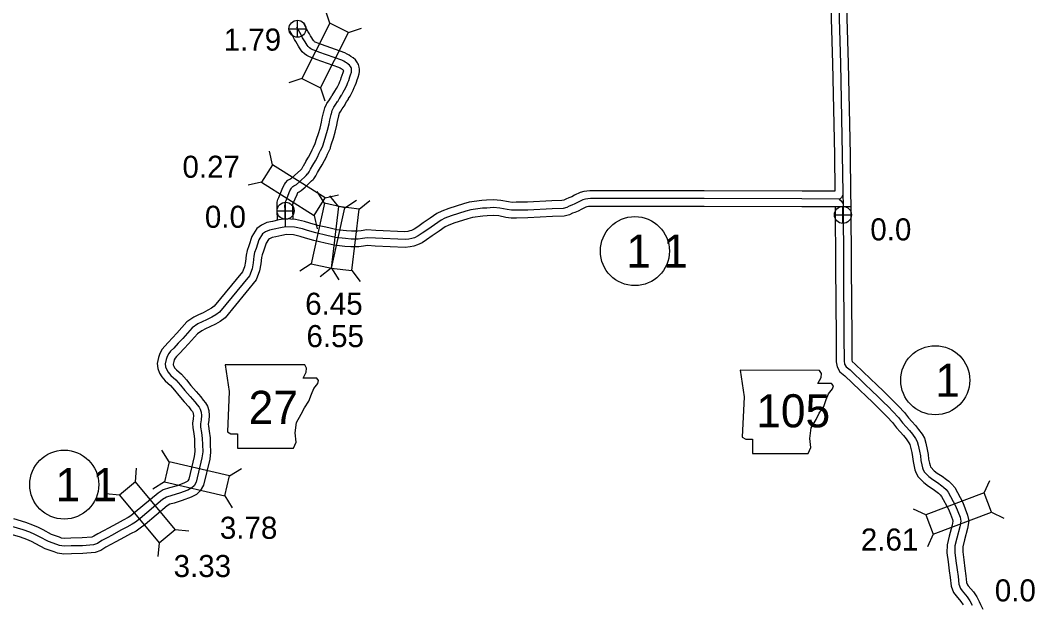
# Model space of a CAD drawing. Extents: x -83719 to 153526, y -11835 to 11446.
# Drawn here: x -1718 to -1071, y 1987 to 2360 of the extents above; entities that cross this region are included whole.
import ezdxf

# ---------------------------------------------------------------- set-up
doc = ezdxf.new("R2010")
doc.units = 0
for name, color, linetype in [('Level 10', 7, 'Continuous'), ('Level 20', 7, 'Continuous'), ('Level 21', 7, 'Continuous'), ('Level 25', 7, 'Continuous'), ('Level 26', 7, 'Continuous'), ('Level 27', 7, 'Continuous'), ('Level 58', 7, 'Continuous'), ('Level 59', 7, 'Continuous')]:
    doc.layers.add(name, color=color, linetype=linetype)

msp = doc.modelspace()

# ---------------------------------------------------------------- linework, layer by layer
at = {"layer": 'Level 10'}
for points in [[(-1193.62, 2424.2), (-1194.65, 2422.94), (-1195.29, 2421.32), (-1196.58, 2417.04), (-1198.52, 2408.98), (-1199.96, 2405.55), (-1201, 2401.06), (-1201.54, 2397.75), (-1201.69, 2394.1), (-1200.9, 2375.22), (-1199.7, 2332.04), (-1198.5, 2273.9), (-1198.17, 2250.64)], [(-1185.85, 2417.91), (-1185.89, 2417.86), (-1186.92, 2414.43), (-1188.99, 2405.85), (-1190.4, 2402.47), (-1191.18, 2399.11), (-1191.58, 2396.73), (-1191.68, 2394.1), (-1190.91, 2375.57), (-1189.7, 2332.28), (-1188.5, 2274.07), (-1188.15, 2249.59), (-1188.16, 2248.15)], [(-1543.62, 2232.75), (-1543.72, 2238.89), (-1543.79, 2241.37), (-1543.74, 2241.98), (-1543.73, 2242.22), (-1543.72, 2242.27), (-1543.47, 2242.95), (-1541.12, 2248.63), (-1540.52, 2249.71), (-1539.66, 2250.18), (-1538.37, 2251.09), (-1536.02, 2253.24), (-1531.81, 2257.15), (-1530.77, 2258.2), (-1530.42, 2258.56), (-1529.12, 2260.39), (-1527.97, 2262.56), (-1527.97, 2262.58), (-1526.78, 2264.62), (-1526.77, 2264.64), (-1524.99, 2267.54), (-1523.67, 2270.14), (-1522.42, 2272.66), (-1521.59, 2274.34), (-1519.67, 2278.15), (-1519.67, 2278.8), (-1519.09, 2280.85), (-1517.88, 2284.4), (-1516.77, 2288.27), (-1515.72, 2292.69), (-1515.3, 2295.04), (-1514.38, 2298.75), (-1514.36, 2298.85), (-1514.02, 2300.32), (-1513.26, 2301.8), (-1512.25, 2303.28), (-1510.5, 2305.83), (-1510.44, 2306.09), (-1509.55, 2307.59), (-1508.36, 2309.4), (-1508.22, 2309.69), (-1507.27, 2311.32), (-1506.33, 2313.07), (-1505.27, 2315.16), (-1504.6, 2316.72), (-1503.99, 2318.13), (-1503.45, 2319.61), (-1503.01, 2320.9), (-1502.98, 2320.96), (-1502.19, 2323.34), (-1501.55, 2325.5), (-1501.35, 2326.97), (-1501.31, 2328.41), (-1501.49, 2329.81), (-1501.92, 2331.41), (-1502.36, 2332.19), (-1502.51, 2332.63), (-1503.93, 2334.4), (-1505.3, 2335.68), (-1506.71, 2336.67), (-1507.8, 2337.34), (-1509.05, 2338.06), (-1510.67, 2338.81), (-1525.5, 2344.15), (-1527.92, 2345.02), (-1528.97, 2345.43), (-1529.61, 2345.76), (-1529.92, 2345.99), (-1530.25, 2346.31), (-1530.59, 2346.75), (-1531.11, 2347.52), (-1531.68, 2348.46), (-1532.49, 2349.78), (-1533.22, 2351.04), (-1533.95, 2352.35), (-1535.03, 2354.3), (-1535.94, 2356.02), (-1536.66, 2357.47)], [(-1553.61, 2232.06), (-1553.72, 2238.66), (-1553.8, 2241.66), (-1553.73, 2242.51), (-1553.71, 2243.58), (-1553.27, 2245.27), (-1552.78, 2246.6), (-1550.13, 2252.98), (-1549.08, 2254.89), (-1548.54, 2255.96), (-1546.94, 2257.58), (-1545.6, 2258.32), (-1544.98, 2258.67), (-1544.64, 2258.91), (-1542.8, 2260.59), (-1538.76, 2264.34), (-1538.12, 2264.98), (-1537.65, 2265.65), (-1537.12, 2266.65), (-1537.04, 2266.86), (-1535.33, 2269.81), (-1535.26, 2269.93), (-1533.72, 2272.42), (-1532.61, 2274.61), (-1531.39, 2277.1), (-1530.54, 2278.81), (-1529.45, 2280.96), (-1528.63, 2283.84), (-1527.42, 2287.39), (-1526.45, 2290.8), (-1525.51, 2294.72), (-1525.09, 2297.13), (-1524.22, 2300.59), (-1524.19, 2300.89), (-1524.07, 2301.27), (-1523.49, 2303.78), (-1522.28, 2306.13), (-1522.16, 2306.5), (-1520.49, 2308.95), (-1519.75, 2310.02), (-1518.85, 2311.53), (-1518.8, 2311.72), (-1517.07, 2314.36), (-1517.04, 2314.42), (-1515.99, 2316.2), (-1515.2, 2317.69), (-1514.34, 2319.39), (-1513.79, 2320.68), (-1513.28, 2321.85), (-1512.88, 2322.93), (-1512.27, 2324.73), (-1512.26, 2324.76), (-1511.73, 2326.34), (-1511.36, 2327.6), (-1511.35, 2327.65), (-1511.63, 2327.9), (-1512.22, 2328.32), (-1512.91, 2328.75), (-1513.65, 2329.17), (-1514.49, 2329.56), (-1528.88, 2334.74), (-1531.42, 2335.65), (-1533.12, 2336.31), (-1534.95, 2337.27), (-1536.4, 2338.35), (-1537.75, 2339.65), (-1538.68, 2340.88), (-1539.52, 2342.1), (-1540.22, 2343.26), (-1541.09, 2344.67), (-1541.92, 2346.12), (-1542.68, 2347.49), (-1543.81, 2349.53), (-1544.83, 2351.44), (-1545.61, 2353)], [(-1318.99, 2250.97), (-1354.38, 2250.97), (-1356.42, 2250.72), (-1358.22, 2250.5), (-1360.62, 2249.86), (-1364.18, 2248.06), (-1366, 2247.05), (-1367.75, 2246.42), (-1369.75, 2245.58), (-1370.96, 2244.94), (-1372.23, 2244.63), (-1378.67, 2244.42), (-1394.22, 2243.62), (-1401.46, 2243.53), (-1403.97, 2243.45), (-1406.26, 2243.81), (-1411.13, 2244.73), (-1415.91, 2245.16), (-1420.27, 2244.84), (-1423.32, 2244.78), (-1431.29, 2243.69), (-1435.03, 2242.61), (-1444.38, 2239.63), (-1448.82, 2237.95), (-1451.89, 2236.38), (-1456.26, 2233.33), (-1460.62, 2230.35), (-1464.2, 2227.95), (-1466.43, 2226.42), (-1468.08, 2225.61), (-1469.2, 2225.25), (-1470.55, 2224.95), (-1472.34, 2224.79), (-1490.82, 2225.55), (-1496.55, 2225.94), (-1500.14, 2225.37), (-1502.4, 2225.09), (-1506.44, 2225.06), (-1509.62, 2225.34), (-1515.8, 2226.08), (-1520.93, 2227.2), (-1527.92, 2228.85), (-1532.89, 2230.25), (-1536.39, 2231.39), (-1542.07, 2232.66), (-1548.45, 2233)], [(-1198.17, 2250.64), (-1219.16, 2250.67), (-1281.52, 2250.89), (-1318.97, 2250.97)], [(-1188.16, 2248.27), (-1188.03, 2242.66), (-1187.76, 2202.47), (-1187.49, 2157.59), (-1187.39, 2142.79), (-1187.25, 2142.06), (-1187.18, 2141.93), (-1185.24, 2140.32), (-1175.44, 2130.96), (-1171.37, 2127.04), (-1167.12, 2123.06), (-1163.94, 2119.88), (-1160.53, 2116.52), (-1157.55, 2113.53), (-1153.87, 2109.51), (-1151.24, 2106.02), (-1149.07, 2103.69), (-1146.85, 2101.11), (-1144.81, 2098.63), (-1142.65, 2095.58), (-1141.17, 2093.02), (-1140.22, 2089.81), (-1139.35, 2085.79), (-1138.77, 2082.55), (-1138.44, 2079.6), (-1137.98, 2077.15), (-1137.56, 2075.66), (-1137.31, 2074.86), (-1137.09, 2074.5), (-1134.92, 2072.27), (-1132.9, 2070.7), (-1129.9, 2068.83), (-1127.11, 2066.68), (-1125.65, 2065.62), (-1123.66, 2063.72), (-1121.83, 2061.52), (-1116.69, 2052.08), (-1115.12, 2048.05), (-1113.59, 2043.97), (-1112.82, 2040.22), (-1113.75, 2035.34), (-1115.62, 2028.12), (-1116.67, 2023.66), (-1116.73, 2020.46), (-1116.05, 2015.37), (-1115.33, 2009.79), (-1114.72, 2005.3), (-1114.27, 2000.97), (-1113.72, 1999.52), (-1113.16, 1998.76), (-1109.83, 1994.92), (-1107.78, 1991.72), (-1106.28, 1988.81), (-1105.29, 1986.89), (-1103.92, 1983.89)], [(-1318.99, 2240.97), (-1353.77, 2240.97), (-1355.19, 2240.79), (-1356.32, 2240.65), (-1357.04, 2240.46), (-1359.51, 2239.21), (-1361.87, 2237.91), (-1364.1, 2237.11), (-1365.48, 2236.52), (-1367.39, 2235.53), (-1370.84, 2234.67), (-1378.25, 2234.43), (-1393.9, 2233.63), (-1401.24, 2233.53), (-1404.59, 2233.43), (-1407.97, 2233.95), (-1412.51, 2234.82), (-1415.99, 2235.13), (-1419.81, 2234.84), (-1422.55, 2234.79), (-1429.21, 2233.88), (-1432.12, 2233.04), (-1441.09, 2230.19), (-1444.76, 2228.8), (-1446.72, 2227.79), (-1450.57, 2225.1), (-1455.01, 2222.07), (-1458.59, 2219.67), (-1461.38, 2217.76), (-1464.32, 2216.32), (-1466.58, 2215.59), (-1469.02, 2215.05), (-1472.09, 2214.77), (-1491.37, 2215.56), (-1496.1, 2215.88), (-1498.75, 2215.47), (-1501.75, 2215.1), (-1506.83, 2215.06), (-1510.65, 2215.39), (-1517.47, 2216.2), (-1523.14, 2217.45), (-1530.42, 2219.16), (-1535.8, 2220.68), (-1539.04, 2221.74), (-1543.43, 2222.72), (-1547.84, 2222.96)], [(-1188.02, 2240.63), (-1219.18, 2240.67), (-1281.54, 2240.89), (-1319, 2240.97)], [(-1198.02, 2240.56), (-1197.76, 2202.41), (-1197.49, 2157.52), (-1197.38, 2141.82), (-1196.76, 2138.56), (-1194.97, 2135.4), (-1191.89, 2132.85), (-1182.36, 2123.75), (-1178.26, 2119.79), (-1174.08, 2115.87), (-1170.99, 2112.79), (-1167.59, 2109.43), (-1164.78, 2106.61), (-1161.57, 2103.11), (-1158.91, 2099.58), (-1156.51, 2097.01), (-1154.5, 2094.67), (-1152.77, 2092.57), (-1151.08, 2090.17), (-1150.42, 2089.04), (-1149.92, 2087.34), (-1149.16, 2083.85), (-1148.67, 2081.11), (-1148.34, 2078.13), (-1147.73, 2074.87), (-1147.14, 2072.78), (-1146.47, 2070.66), (-1145.03, 2068.32), (-1141.6, 2064.8), (-1138.62, 2062.48), (-1135.61, 2060.61), (-1133.1, 2058.67), (-1132.07, 2057.92), (-1130.99, 2056.89), (-1130.15, 2055.88), (-1125.78, 2047.85), (-1124.46, 2044.47), (-1123.23, 2041.2), (-1123.02, 2040.16), (-1123.52, 2037.53), (-1125.33, 2030.52), (-1126.65, 2024.91), (-1126.74, 2019.9), (-1125.97, 2014.07), (-1125.24, 2008.48), (-1124.65, 2004.11), (-1124.09, 1998.65), (-1122.58, 1994.68), (-1120.95, 1992.48), (-1117.86, 1988.92), (-1116.46, 1986.73)], [(-1548.45, 2233), (-1552.66, 2232.26), (-1556.81, 2231.37), (-1560.26, 2230.62), (-1563.81, 2228.97), (-1566.78, 2226.83), (-1570, 2221.64), (-1571.9, 2215.7), (-1572.99, 2212.87), (-1573.55, 2209.89), (-1574.05, 2205.76), (-1574.64, 2202.41), (-1575.85, 2199.26), (-1593.9, 2177.23), (-1595.67, 2175.98), (-1597.89, 2174.65), (-1601.03, 2173.09), (-1603.84, 2171.76), (-1606.83, 2170.22), (-1611.27, 2167.21), (-1617.71, 2160.04), (-1620.47, 2156.99), (-1623.28, 2154), (-1625.4, 2151.83), (-1627.06, 2149.83), (-1628.56, 2147.1), (-1629.41, 2144.52), (-1630.22, 2140.67), (-1629.79, 2137.4), (-1628.7, 2134.48), (-1627.35, 2132.29), (-1625.21, 2129.58), (-1621.81, 2126.7), (-1619.14, 2123.72), (-1616.46, 2120.36), (-1613.03, 2116.34), (-1610.14, 2113), (-1608.72, 2111.19), (-1607.75, 2109.97), (-1607.55, 2109.6), (-1607.25, 2108.64), (-1607.11, 2107.42), (-1607.27, 2105.38), (-1607.68, 2102.62), (-1607.61, 2099.64), (-1606.98, 2096.02), (-1606.53, 2092.43), (-1606.44, 2088.91), (-1606.28, 2084.49), (-1606.67, 2081.37), (-1610.07, 2066.8), (-1610.65, 2065.8), (-1611.1, 2065.4), (-1612.78, 2064.5), (-1617.54, 2062.72), (-1622.35, 2061.26), (-1626.4, 2060.07), (-1629.75, 2057.93), (-1644.33, 2045.77), (-1647.11, 2043.57), (-1648.85, 2042.35), (-1651.86, 2040.77), (-1655.8, 2038.68), (-1661.37, 2035.63), (-1664.59, 2033.93), (-1668.01, 2032.05), (-1670.56, 2030.45), (-1671.9, 2029.98), (-1678.12, 2029.42), (-1685.3, 2029.3), (-1689.46, 2029.11), (-1691.28, 2029.35), (-1692.52, 2029.82), (-1697.56, 2031.63), (-1703.02, 2034.5), (-1706.04, 2036.07), (-1709.65, 2037.61), (-1714.05, 2039.35), (-1721.72, 2041.64)], [(-1547.84, 2222.96), (-1550.74, 2222.44), (-1554.71, 2221.59), (-1557.04, 2221.09), (-1558.73, 2220.3), (-1559.33, 2219.87), (-1560.85, 2217.42), (-1562.46, 2212.38), (-1563.33, 2210.12), (-1563.66, 2208.36), (-1564.16, 2204.28), (-1564.96, 2199.73), (-1567.09, 2194.18), (-1587.02, 2169.85), (-1590.21, 2167.59), (-1593.1, 2165.87), (-1596.66, 2164.1), (-1599.41, 2162.79), (-1601.73, 2161.61), (-1604.64, 2159.62), (-1610.28, 2153.34), (-1613.12, 2150.21), (-1616.06, 2147.08), (-1617.97, 2145.14), (-1618.75, 2144.19), (-1619.35, 2143.09), (-1619.74, 2141.92), (-1620.08, 2140.29), (-1620.02, 2139.83), (-1619.67, 2138.89), (-1619.14, 2138.03), (-1617.98, 2136.57), (-1614.82, 2133.89), (-1611.5, 2130.18), (-1608.74, 2126.72), (-1605.45, 2122.86), (-1602.42, 2119.37), (-1600.88, 2117.4), (-1599.37, 2115.5), (-1598.28, 2113.49), (-1597.42, 2110.72), (-1597.06, 2107.61), (-1597.33, 2104.24), (-1597.67, 2101.98), (-1597.63, 2100.63), (-1597.09, 2097.52), (-1596.54, 2093.18), (-1596.44, 2089.22), (-1596.26, 2084.04), (-1596.81, 2079.61), (-1600.68, 2063.03), (-1602.79, 2059.46), (-1605.25, 2057.17), (-1608.67, 2055.36), (-1614.34, 2053.24), (-1619.49, 2051.68), (-1622.21, 2050.88), (-1623.83, 2049.85), (-1638.03, 2038.01), (-1641.13, 2035.55), (-1643.63, 2033.8), (-1647.19, 2031.92), (-1651.06, 2029.87), (-1656.64, 2026.82), (-1659.84, 2025.13), (-1662.93, 2023.43), (-1666.21, 2021.37), (-1669.78, 2020.13), (-1677.59, 2019.43), (-1684.99, 2019.3), (-1689.89, 2019.08), (-1693.73, 2019.59), (-1695.97, 2020.43), (-1701.6, 2022.46), (-1707.65, 2025.64), (-1710.31, 2027.02), (-1713.45, 2028.36), (-1717.33, 2029.89), (-1724, 2031.88)]]:
    msp.add_lwpolyline(points, dxfattribs=at)
at = {"layer": 'Level 20'}
for p, q in [((-1520.18, 2357.86), (-1522.94, 2366.21)), ((-1508.38, 2351.92), (-1500.03, 2354.69)), ((-1537.97, 2322.48), (-1546.33, 2319.72)), ((-1526.18, 2316.55), (-1523.42, 2308.19)), ((-1556.71, 2267.5), (-1558.64, 2276.09)), ((-1563.76, 2256.34), (-1572.34, 2254.41)), ((-1523.51, 2242.93), (-1528.25, 2250.34)), ((-1523.23, 2246.35), (-1514.65, 2248.28)), ((-1514.66, 2240.85), (-1520.1, 2247.76)), ((-1510.62, 2240.09), (-1503.2, 2244.83)), ((-1501.55, 2239.27), (-1494.63, 2244.71)), ((-1530.28, 2235.19), (-1528.35, 2226.61)), ((-1532.02, 2204.25), (-1539.43, 2199.51)), ((-1519.37, 2201.53), (-1526.29, 2196.09)), ((-1519.13, 2201.42), (-1514.39, 2194)), ((-1506.27, 2199.96), (-1500.83, 2193.04)), ((-1622.65, 2078.02), (-1627.29, 2085.49)), ((-1644.2, 2065.15), (-1643.41, 2073.91)), ((-1584.08, 2069.01), (-1576.61, 2073.66)), ((-1625.65, 2065.16), (-1633.12, 2060.52)), ((-1103.08, 2058.09), (-1099.45, 2066.11)), ((-1654.34, 2056.69), (-1663.1, 2057.49)), ((-1587.09, 2056.16), (-1582.44, 2048.68)), ((-1140.15, 2044.16), (-1148.17, 2047.8)), ((-1098.44, 2045.74), (-1090.43, 2042.1)), ((-1618.84, 2034.74), (-1610.07, 2033.95)), ((-1135.51, 2031.81), (-1139.14, 2023.79)), ((-1628.97, 2026.28), (-1629.77, 2017.52))]:
    msp.add_line(p, q, dxfattribs=at)
for points in [[(-1526.18, 2316.55), (-1508.38, 2351.92), (-1520.18, 2357.86), (-1537.97, 2322.48)], [(-1563.76, 2256.34), (-1530.28, 2235.19), (-1523.23, 2246.35), (-1556.71, 2267.5)], [(-1519.13, 2201.42), (-1510.62, 2240.09), (-1523.51, 2242.93), (-1532.02, 2204.25)], [(-1514.66, 2240.85), (-1519.37, 2201.53), (-1506.27, 2199.96), (-1501.55, 2239.27)], [(-1584.08, 2069.01), (-1622.65, 2078.02), (-1625.65, 2065.16), (-1587.09, 2056.16)], [(-1654.34, 2056.69), (-1628.97, 2026.28), (-1618.84, 2034.74), (-1644.2, 2065.15)], [(-1103.08, 2058.09), (-1140.15, 2044.16), (-1135.51, 2031.81), (-1098.44, 2045.74)]]:
    msp.add_lwpolyline(points, close=True, dxfattribs=at)
at = {"layer": 'Level 21'}
for points in [[(-1586.87, 2139.77), (-1584.34, 2122.85), (-1585.46, 2097.19), (-1583.21, 2095.78), (-1578.98, 2095.78), (-1578.98, 2086.76), (-1543.45, 2086.76), (-1541.76, 2090.42), (-1542.32, 2096.35), (-1541.48, 2103.11), (-1538.38, 2108.47), (-1536.4, 2112.42), (-1533.58, 2116.65), (-1531.89, 2121.16), (-1530.48, 2124.82), (-1527.94, 2127.93), (-1527.38, 2129.9), (-1528.51, 2131.31), (-1537.25, 2131.31), (-1535.27, 2135.26), (-1534.99, 2137.8), (-1536.16, 2139.74)], [(-1258.65, 2136.35), (-1256.11, 2119.43), (-1257.24, 2093.78), (-1254.98, 2092.37), (-1250.75, 2092.37), (-1250.75, 2083.34), (-1215.22, 2083.34), (-1213.53, 2087.01), (-1214.1, 2092.93), (-1213.25, 2099.7), (-1210.15, 2105.05), (-1208.17, 2109), (-1205.35, 2113.23), (-1203.66, 2117.74), (-1202.25, 2121.41), (-1199.72, 2124.51), (-1199.15, 2126.48), (-1200.28, 2127.89), (-1209.02, 2127.89), (-1207.05, 2131.84), (-1206.76, 2134.38), (-1207.93, 2136.33)]]:
    msp.add_lwpolyline(points, close=True, dxfattribs=at)
at = {"layer": 'Level 26'}
for p, q in [((-1546.28, 2354.27), (-1535.44, 2354.27)), ((-1540.86, 2348.85), (-1540.86, 2359.68)), ((-1553.79, 2238.18), (-1542.95, 2238.18)), ((-1548.37, 2232.77), (-1548.37, 2243.6)), ((-1193.06, 2230.11), (-1193.06, 2240.95)), ((-1198.48, 2235.53), (-1187.64, 2235.53))]:
    msp.add_line(p, q, dxfattribs=at)
for centre in [(-1540.86, 2354.27), (-1548.37, 2238.18), (-1193.06, 2235.53)]:
    msp.add_circle(centre, 5.42, dxfattribs=at)
at = {"layer": 'Level 27'}
for centre in [(-1325.71, 2212.41), (-1134.2, 2130.01), (-1689.55, 2063.41)]:
    msp.add_circle(centre, 22, dxfattribs=at)
at = {"layer": 'Level 59'}
for points in [[(-1189.74, 2421.06), (-1190.29, 2420.38), (-1190.57, 2419.67), (-1191.75, 2415.74), (-1193.76, 2407.42), (-1195.18, 2404.01), (-1196.09, 2400.09), (-1196.56, 2397.24), (-1196.69, 2394.1), (-1195.9, 2375.39), (-1194.7, 2332.16), (-1193.5, 2273.98), (-1193.15, 2249.56), (-1193.16, 2248.16)], [(-1548.54, 2228), (-1548.72, 2238.77), (-1548.8, 2241.51), (-1548.74, 2242.25), (-1548.72, 2242.9), (-1548.5, 2243.77), (-1548.13, 2244.77), (-1545.62, 2250.8), (-1544.66, 2252.55), (-1544.43, 2253.01), (-1543.89, 2253.56), (-1543.18, 2253.95), (-1542.32, 2254.43), (-1541.5, 2255), (-1539.41, 2256.91), (-1535.29, 2260.74), (-1534.35, 2261.69), (-1534.28, 2261.76), (-1533.38, 2263.02), (-1532.54, 2264.61), (-1532.5, 2264.72), (-1531.05, 2267.21), (-1531.01, 2267.28), (-1529.35, 2269.98), (-1528.14, 2272.38), (-1526.9, 2274.88), (-1526.06, 2276.57), (-1524.67, 2279.34), (-1524.67, 2279.5), (-1523.86, 2282.35), (-1522.65, 2285.9), (-1521.61, 2289.53), (-1520.62, 2293.7), (-1520.19, 2296.09), (-1519.3, 2299.67), (-1519.28, 2299.82), (-1519.24, 2299.96), (-1518.76, 2302.05), (-1517.64, 2304.22), (-1517.62, 2304.29), (-1516.37, 2306.11), (-1515.21, 2307.8), (-1515.19, 2307.9), (-1514.16, 2309.62), (-1514.14, 2309.7), (-1512.71, 2311.88), (-1512.63, 2312.06), (-1511.63, 2313.76), (-1510.76, 2315.38), (-1509.8, 2317.28), (-1509.19, 2318.7), (-1508.63, 2319.99), (-1508.16, 2321.27), (-1507.64, 2322.81), (-1507.62, 2322.86), (-1506.96, 2324.84), (-1506.46, 2326.55), (-1506.34, 2327.38), (-1506.32, 2328.16), (-1506.41, 2328.85), (-1506.58, 2329.49), (-1506.96, 2330.15), (-1506.99, 2330.22), (-1507.6, 2330.98), (-1508.47, 2331.79), (-1509.47, 2332.5), (-1510.35, 2333.04), (-1511.35, 2333.61), (-1512.58, 2334.19), (-1527.19, 2339.44), (-1529.67, 2340.34), (-1531.05, 2340.87), (-1532.28, 2341.52), (-1533.16, 2342.17), (-1534, 2342.98), (-1534.63, 2343.82), (-1535.32, 2344.81), (-1535.95, 2345.86), (-1536.79, 2347.23), (-1537.57, 2348.58), (-1538.31, 2349.92), (-1539.42, 2351.92), (-1540.39, 2353.73), (-1541.14, 2355.24)], [(-1318.99, 2245.97), (-1354.07, 2245.97), (-1355.8, 2245.75), (-1357.27, 2245.58), (-1358.83, 2245.16), (-1361.85, 2243.64), (-1363.93, 2242.48), (-1365.93, 2241.77), (-1367.62, 2241.05), (-1369.18, 2240.24), (-1371.54, 2239.65), (-1378.46, 2239.42), (-1394.06, 2238.63), (-1401.35, 2238.53), (-1404.28, 2238.44), (-1407.12, 2238.88), (-1411.82, 2239.78), (-1415.95, 2240.14), (-1420.04, 2239.84), (-1422.94, 2239.78), (-1430.25, 2238.79), (-1433.57, 2237.82), (-1442.74, 2234.91), (-1446.79, 2233.37), (-1449.31, 2232.09), (-1453.41, 2229.22), (-1457.82, 2226.21), (-1461.39, 2223.81), (-1463.91, 2222.09), (-1466.2, 2220.97), (-1467.89, 2220.42), (-1469.78, 2220), (-1472.21, 2219.78), (-1491.09, 2220.56), (-1496.32, 2220.91), (-1499.45, 2220.42), (-1502.08, 2220.1), (-1506.64, 2220.06), (-1510.14, 2220.36), (-1516.63, 2221.14), (-1522.04, 2222.33), (-1529.17, 2224), (-1534.34, 2225.46), (-1537.72, 2226.57), (-1542.75, 2227.69), (-1548.15, 2227.98)], [(-1195.46, 2245.64), (-1219.17, 2245.67), (-1281.53, 2245.89), (-1318.99, 2245.97)], [(-1193.16, 2248.16), (-1193.95, 2246.67), (-1194.87, 2245.78), (-1195.46, 2245.64)], [(-1195.46, 2245.64), (-1194.14, 2244.53), (-1193.03, 2242.59)], [(-1193.16, 2248.16), (-1193.03, 2242.59), (-1192.76, 2202.44), (-1192.49, 2157.56), (-1192.38, 2142.31), (-1192.01, 2140.31), (-1191.07, 2138.66), (-1188.56, 2136.58), (-1178.9, 2127.36), (-1174.82, 2123.41), (-1170.6, 2119.47), (-1167.47, 2116.34), (-1164.06, 2112.97), (-1161.17, 2110.07), (-1157.72, 2106.31), (-1155.08, 2102.8), (-1152.79, 2100.35), (-1150.67, 2097.89), (-1148.79, 2095.6), (-1146.87, 2092.87), (-1145.79, 2091.03), (-1145.07, 2088.57), (-1144.25, 2084.82), (-1143.72, 2081.83), (-1143.39, 2078.87), (-1142.86, 2076.01), (-1142.35, 2074.22), (-1141.89, 2072.76), (-1141.06, 2071.41), (-1138.26, 2068.53), (-1135.76, 2066.59), (-1132.75, 2064.72), (-1130.11, 2062.68), (-1128.86, 2061.77), (-1127.33, 2060.3), (-1125.99, 2058.7), (-1121.23, 2049.96), (-1119.79, 2046.26), (-1118.41, 2042.58), (-1117.92, 2040.19), (-1118.63, 2036.44), (-1120.47, 2029.32), (-1121.66, 2024.29), (-1121.73, 2020.18), (-1121.01, 2014.72), (-1120.29, 2009.13), (-1119.69, 2004.71), (-1119.18, 1999.81), (-1118.15, 1997.1), (-1117.06, 1995.62), (-1113.84, 1991.92), (-1112.12, 1989.22), (-1110.73, 1986.52)], [(-1548.15, 2227.98), (-1551.7, 2227.35), (-1555.76, 2226.48), (-1558.65, 2225.86), (-1561.27, 2224.63), (-1563.06, 2223.35), (-1565.42, 2219.53), (-1567.18, 2214.04), (-1568.16, 2211.5), (-1568.6, 2209.12), (-1569.1, 2205.02), (-1569.8, 2201.07), (-1571.47, 2196.72), (-1590.46, 2173.54), (-1592.94, 2171.78), (-1595.49, 2170.26), (-1598.84, 2168.6), (-1601.63, 2167.27), (-1604.28, 2165.92), (-1607.96, 2163.42), (-1613.99, 2156.69), (-1616.8, 2153.6), (-1619.67, 2150.54), (-1621.69, 2148.49), (-1622.91, 2147.01), (-1623.96, 2145.1), (-1624.57, 2143.22), (-1625.15, 2140.48), (-1624.9, 2138.62), (-1624.19, 2136.69), (-1623.24, 2135.16), (-1621.6, 2133.07), (-1618.31, 2130.3), (-1615.32, 2126.95), (-1612.6, 2123.54), (-1609.24, 2119.6), (-1606.28, 2116.19), (-1604.8, 2114.3), (-1603.56, 2112.74), (-1602.92, 2111.54), (-1602.33, 2109.68), (-1602.08, 2107.51), (-1602.3, 2104.81), (-1602.68, 2102.3), (-1602.62, 2100.13), (-1602.03, 2096.77), (-1601.53, 2092.8), (-1601.44, 2089.07), (-1601.27, 2084.26), (-1601.74, 2080.49), (-1605.37, 2064.91), (-1606.72, 2062.63), (-1608.17, 2061.28), (-1610.73, 2059.93), (-1615.94, 2057.98), (-1620.92, 2056.47), (-1624.31, 2055.48), (-1626.79, 2053.89), (-1641.18, 2041.89), (-1644.12, 2039.56), (-1646.24, 2038.08), (-1649.52, 2036.35), (-1653.43, 2034.28), (-1659, 2031.23), (-1662.22, 2029.53), (-1665.47, 2027.74), (-1668.38, 2025.91), (-1670.84, 2025.06), (-1677.86, 2024.43), (-1685.15, 2024.3), (-1689.67, 2024.1), (-1692.51, 2024.47), (-1694.24, 2025.12), (-1699.58, 2027.05), (-1705.33, 2030.07), (-1708.18, 2031.55), (-1711.55, 2032.99), (-1715.69, 2034.62), (-1722.86, 2036.76)]]:
    msp.add_lwpolyline(points, dxfattribs=at)

# ---------------------------------------------------------------- texts
at = {"layer": 'Level 21'}
for s, p in [('27', (-1571.98, 2102.14)), ('105', (-1248.34, 2099.95))]:
    msp.add_text(s, height=21.12, dxfattribs=at).set_placement(p)
at = {"layer": 'Level 25'}
for s, p in [('1.79', (-1587.88, 2340.33)), ('0.0', (-1599.85, 2227.28)), ('0.0', (-1175.62, 2219.24)), ('0.0', (-1096.24, 1988.89))]:
    msp.add_text(s, height=14.08, dxfattribs=at).set_placement(p)
at = {"layer": 'Level 27'}
for s, p in [('1 1', (-1331.22, 2201.85)), ('1', (-1134.2, 2119.45)), ('1 1', (-1695.06, 2052.85))]:
    msp.add_text(s, height=21.12, dxfattribs=at).set_placement(p)
at = {"layer": 'Level 58'}
for s, p in [('0.27', (-1614.16, 2259.19)), ('6.45', (-1535.91, 2171.77)), ('6.55', (-1535.11, 2151.13)), ('3.78', (-1590.3, 2028.84)), ('2.61', (-1181.65, 2021.34)), ('3.33', (-1619.8, 2004.44))]:
    msp.add_text(s, height=14.08, dxfattribs=at).set_placement(p)

doc.saveas('drawing.dxf')
